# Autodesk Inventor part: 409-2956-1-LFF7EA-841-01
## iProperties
Created: 2010-09
Part Number: 409-2956-1-LFF7EA-841-01
Material: 1/2"OD TUBE - SS
Document SubType Name: Modeling
Designer: S. Boerckel
Engineer: Steve Boerckel
Mass: 246.219 g
Surface Area: 534.036 cm^2
Volume: 30.4727 cm^3
Density: 8.08 g/cm^3
Description: BACK PRESSURE TUBE
Length: 28.909 in
Author: S. Boerckel
Revision Number: 0
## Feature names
1. Sweep2
